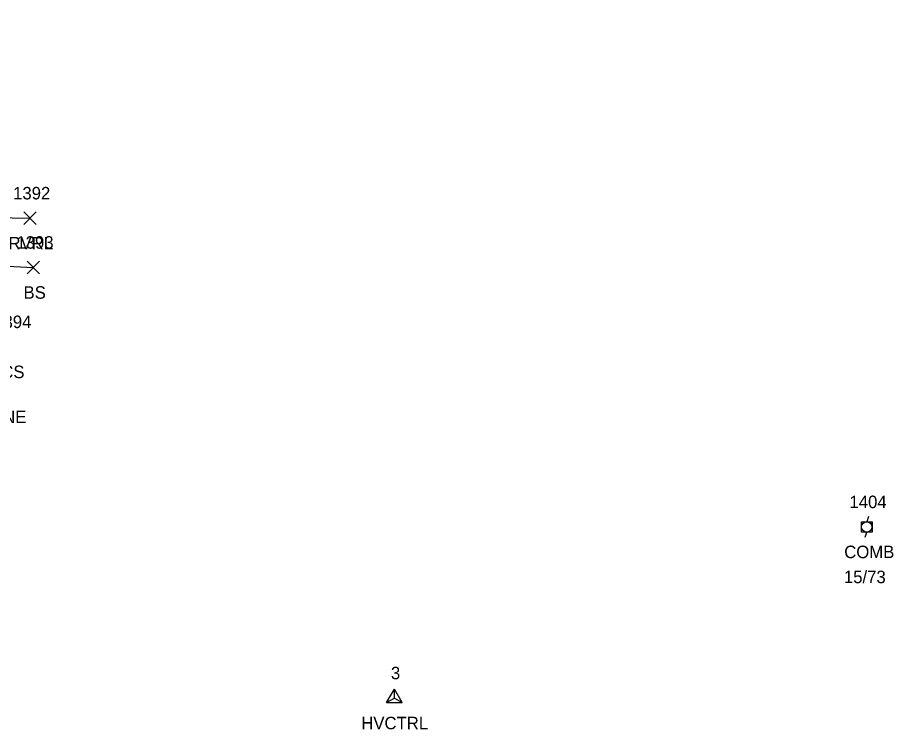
# Model space of a CAD drawing. Extents: x 1514253 to 1516033, y 782541 to 785002.
# Drawn here: x 1515460.6 to 1515600.8, y 782648.4 to 782762.3 of the extents above; entities that cross this region are included whole.
import ezdxf

# ---------------------------------------------------------------- set-up
doc = ezdxf.new("R2010")
doc.units = 0
for name, color, linetype in [('C_A', 7, 'Continuous'), ('C_I', 7, 'Continuous'), ('CPSM', 7, 'Continuous'), ('L_A', 7, 'Continuous'), ('L_I', 7, 'Continuous'), ('L_TIC', 7, 'Continuous'), ('LAWE', 7, 'Continuous'), ('LELB', 7, 'Continuous'), ('U_A', 7, 'Continuous'), ('U_C', 7, 'Continuous'), ('U_I', 7, 'Continuous'), ('UP', 7, 'Continuous')]:
    doc.layers.add(name, color=color, linetype=linetype)

msp = doc.modelspace()

# ---------------------------------------------------------------- linework, layer by layer
at = {"layer": 'CPSM'}
for p, q in [((1515519.65, 782652.72), (1515520.9, 782654.88)), ((1515522.15, 782652.72), (1515520.9, 782654.88)), ((1515520.9, 782653.44), (1515520.9, 782654.88)), ((1515519.65, 782652.72), (1515520.9, 782653.44)), ((1515519.65, 782652.72), (1515522.15, 782652.72)), ((1515520.9, 782653.44), (1515520.9, 782653.44)), ((1515520.9, 782653.44), (1515522.15, 782652.72))]:
    msp.add_line(p, q, dxfattribs=at)
at = {"layer": 'L_TIC'}
for points in [[(1515461.57, 782729.18), (1515463.57, 782731.18)], [(1515463.57, 782729.18), (1515461.57, 782731.18)], [(1515462.1, 782721.3), (1515464.1, 782723.3)], [(1515464.1, 782721.3), (1515462.1, 782723.3)]]:
    msp.add_lwpolyline(points, dxfattribs=at)
at = {"layer": 'LAWE'}
msp.add_lwpolyline([(1515202.17, 782762.27), (1515243.71, 782756.27), (1515286.28, 782747.11), (1515297.44, 782750.04), (1515300.76, 782752.52), (1515315.46, 782751.02), (1515328.64, 782746.75), (1515343.2, 782744.52), (1515396.17, 782730.21), (1515410.48, 782726.67), (1515425.65, 782730.86), (1515462.57, 782730.18)], dxfattribs=at)
at = {"layer": 'LELB'}
msp.add_lwpolyline([(1515428.11, 782724.13), (1515463.1, 782722.3)], dxfattribs=at)
at = {"layer": 'UP'}
for p, q in [((1515596.75, 782682.47), (1515596.5, 782681.64)), ((1515595.67, 782679.97), (1515595.67, 782681.64)), ((1515595.67, 782681.64), (1515597.34, 782681.64)), ((1515596.5, 782680.81), (1515596.5, 782680.81)), ((1515597.34, 782681.64), (1515597.34, 782679.97)), ((1515597.34, 782679.97), (1515595.67, 782679.97)), ((1515596.25, 782679.14), (1515596.5, 782679.97))]:
    msp.add_line(p, q, dxfattribs=at)
msp.add_circle((1515596.5, 782680.81), 0.833, dxfattribs=at)

# ---------------------------------------------------------------- texts
at = {"layer": 'C_A'}
msp.add_text('HVCTRL', height=2, dxfattribs=at).set_placement((1515515.59, 782648.44))
at = {"layer": 'C_I'}
msp.add_text('3', height=2, dxfattribs=at).set_placement((1515520.34, 782656.44))
at = {"layer": 'L_A'}
for s, p in [('RVRL', (1515459.13, 782725.18)), ('BS', (1515461.54, 782717.3)), ('CS', (1515457.98, 782704.6)), ('STONE', (1515452.78, 782697.4))]:
    msp.add_text(s, height=2, dxfattribs=at).set_placement(p)
at = {"layer": 'L_I'}
for s, p in [('1392', (1515459.87, 782733.18)), ('1393', (1515460.4, 782725.3)), ('1394', (1515456.85, 782712.6))]:
    msp.add_text(s, height=2, dxfattribs=at).set_placement(p)
at = {"layer": 'U_A'}
msp.add_text('COMB', height=2, dxfattribs=at).set_placement((1515592.89, 782675.81))
at = {"layer": 'U_C'}
msp.add_text('15/73', height=2, dxfattribs=at).set_placement((1515592.84, 782671.81))
at = {"layer": 'U_I'}
msp.add_text('1404', height=2, dxfattribs=at).set_placement((1515593.73, 782683.81))

doc.saveas('drawing.dxf')
